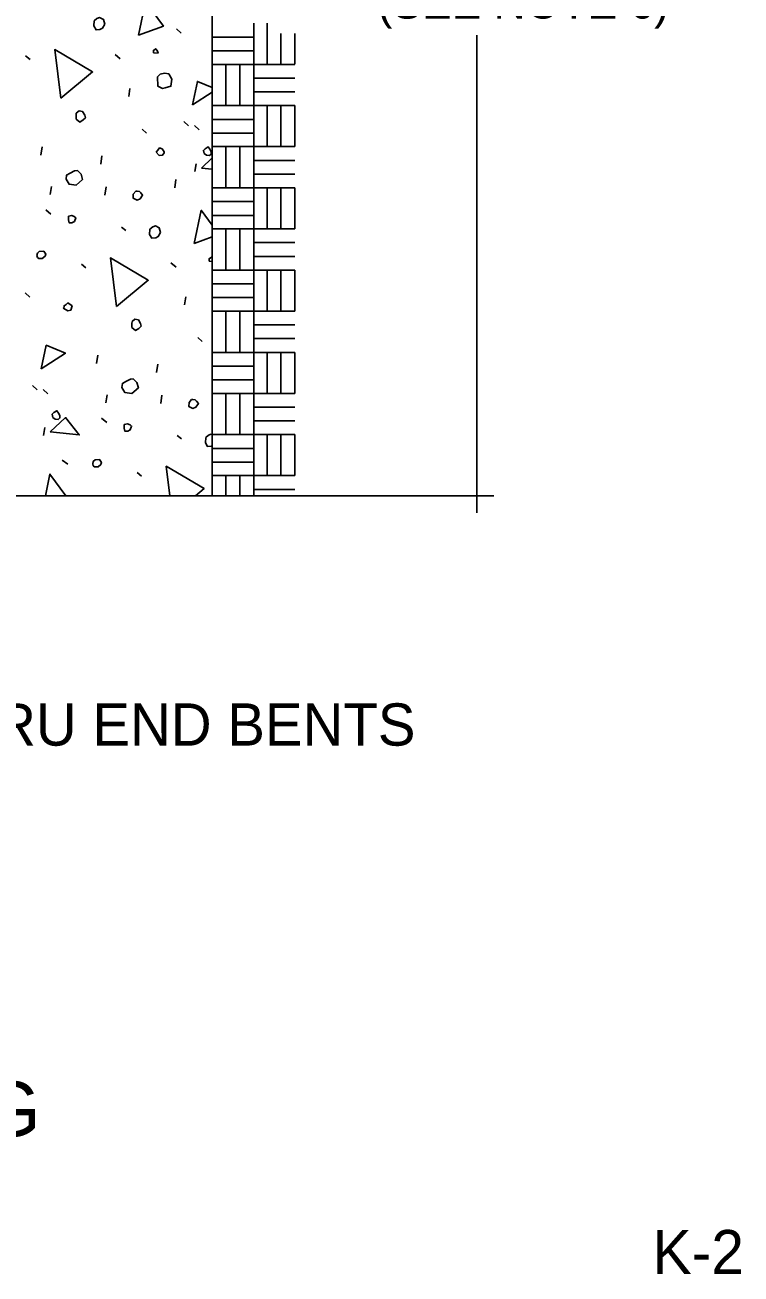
# Model space of a CAD drawing. Extents: x -1660015.2 to -1659984.9, y 2580594.2 to 2580616.7.
# Drawn here: x -1659988.32 to -1659985.07, y 2580594.23 to 2580599.91 of the extents above; entities that cross this region are included whole.
import ezdxf

# ---------------------------------------------------------------- set-up
doc = ezdxf.new("R2010")
doc.units = 0
for name, color, linetype in [('Miscellaneous', 7, 'Continuous'), ('Miscellaneous3', 7, 'Continuous'), ('Miscellaneous4', 7, 'Continuous'), ('PlotBorder_dp', 7, 'Continuous'), ('SheetLines_dp', 7, 'Continuous'), ('TextShtNo', 7, 'Continuous')]:
    doc.layers.add(name, color=color, linetype=linetype)

msp = doc.modelspace()

# ---------------------------------------------------------------- linework, layer by layer
at = {"layer": 'Miscellaneous'}
for p, q in [((-1659987.2832, 2580599.5396), (-1659987.2832, 2580599.9134)), ((-1659987.2219, 2580599.7271), (-1659987.2219, 2580599.9134)), ((-1659987.6339, 2580599.8883), (-1659987.613, 2580599.868)), ((-1659987.4719, 2580599.8509), (-1659987.2832, 2580599.8509)), ((-1659987.1594, 2580599.7272), (-1659987.1594, 2580599.8675)), ((-1659987.0969, 2580599.7272), (-1659987.0969, 2580599.8675)), ((-1659987.4719, 2580599.7884), (-1659987.2832, 2580599.7884)), ((-1659988.3208, 2580599.7663), (-1659988.3005, 2580599.7485)), ((-1659987.9134, 2580599.772), (-1659987.89, 2580599.7524)), ((-1659987.4719, 2580599.7271), (-1659987.0969, 2580599.7271)), ((-1659987.4094, 2580599.7271), (-1659987.4094, 2580599.5396)), ((-1659987.3469, 2580599.7271), (-1659987.3469, 2580599.5396)), ((-1659987.8519, 2580599.5814), (-1659987.8459, 2580599.6167)), ((-1659987.2832, 2580599.6646), (-1659987.0969, 2580599.6646)), ((-1659987.2832, 2580599.6021), (-1659987.0969, 2580599.6021)), ((-1659987.4719, 2580599.5396), (-1659987.2832, 2580599.5396)), ((-1659987.2832, 2580599.1659), (-1659987.2832, 2580599.5396)), ((-1659987.2832, 2580599.5396), (-1659987.0969, 2580599.5396)), ((-1659987.2219, 2580599.3534), (-1659987.2219, 2580599.5396)), ((-1659987.1594, 2580599.3534), (-1659987.1594, 2580599.5396)), ((-1659987.0969, 2580599.3534), (-1659987.0969, 2580599.5396)), ((-1659987.6014, 2580599.4673), (-1659987.5804, 2580599.4471)), ((-1659987.5526, 2580599.4494), (-1659987.5316, 2580599.4291)), ((-1659987.4719, 2580599.4771), (-1659987.2832, 2580599.4771)), ((-1659987.7912, 2580599.432), (-1659987.7709, 2580599.4142)), ((-1659987.4719, 2580599.4146), (-1659987.2832, 2580599.4146)), ((-1659988.2513, 2580599.3139), (-1659988.2459, 2580599.3516)), ((-1659987.4719, 2580599.3534), (-1659987.0969, 2580599.3534)), ((-1659987.4719, 2580599.3534), (-1659987.4719, 2580599.1659)), ((-1659987.4094, 2580599.3534), (-1659987.4094, 2580599.1659)), ((-1659987.3469, 2580599.3534), (-1659987.3469, 2580599.1659)), ((-1659987.9789, 2580599.273), (-1659987.9735, 2580599.3107)), ((-1659987.5509, 2580599.2402), (-1659987.5448, 2580599.2755)), ((-1659987.2832, 2580599.2909), (-1659987.0969, 2580599.2909)), ((-1659987.2832, 2580599.2284), (-1659987.0969, 2580599.2284)), ((-1659988.2089, 2580599.1363), (-1659988.2028, 2580599.1716)), ((-1659987.9596, 2580599.1332), (-1659987.9542, 2580599.1709)), ((-1659987.6424, 2580599.1665), (-1659987.637, 2580599.2042)), ((-1659987.4719, 2580599.1659), (-1659987.2832, 2580599.1659)), ((-1659987.2832, 2580599.1659), (-1659987.0969, 2580599.1659)), ((-1659987.2832, 2580598.7921), (-1659987.2832, 2580599.1659)), ((-1659987.2219, 2580598.9796), (-1659987.2219, 2580599.1659)), ((-1659987.1594, 2580598.9796), (-1659987.1594, 2580599.1659)), ((-1659987.0969, 2580598.9796), (-1659987.0969, 2580599.1659)), ((-1659987.4719, 2580599.1034), (-1659987.2832, 2580599.1034)), ((-1659988.229, 2580599.0663), (-1659988.2056, 2580599.0466)), ((-1659987.4719, 2580599.0409), (-1659987.2832, 2580599.0409)), ((-1659987.8844, 2580598.9878), (-1659987.8647, 2580598.9723)), ((-1659987.4719, 2580598.9796), (-1659987.0969, 2580598.9796)), ((-1659987.4719, 2580598.9796), (-1659987.4719, 2580598.7921)), ((-1659987.4094, 2580598.9796), (-1659987.4094, 2580598.7921)), ((-1659987.3469, 2580598.9796), (-1659987.3469, 2580598.7921)), ((-1659987.2832, 2580598.9171), (-1659987.0969, 2580598.9171)), ((-1659988.0671, 2580598.8197), (-1659988.0468, 2580598.8019)), ((-1659987.6597, 2580598.8254), (-1659987.6363, 2580598.8058)), ((-1659987.2832, 2580598.8546), (-1659987.0969, 2580598.8546)), ((-1659987.4719, 2580598.7921), (-1659987.2832, 2580598.7921)), ((-1659987.2832, 2580598.4184), (-1659987.2832, 2580598.7921)), ((-1659987.2832, 2580598.7921), (-1659987.0969, 2580598.7921)), ((-1659987.2219, 2580598.6059), (-1659987.2219, 2580598.7921)), ((-1659987.1594, 2580598.6059), (-1659987.1594, 2580598.7921)), ((-1659987.0969, 2580598.6059), (-1659987.0969, 2580598.7921)), ((-1659987.4719, 2580598.7296), (-1659987.2832, 2580598.7296)), ((-1659988.3221, 2580598.6893), (-1659988.3011, 2580598.669)), ((-1659987.5983, 2580598.6348), (-1659987.5922, 2580598.6701)), ((-1659987.4719, 2580598.6671), (-1659987.2832, 2580598.6671)), ((-1659987.4719, 2580598.6059), (-1659987.0969, 2580598.6059)), ((-1659987.4719, 2580598.6059), (-1659987.4719, 2580598.4184)), ((-1659987.4094, 2580598.6059), (-1659987.4094, 2580598.4184)), ((-1659987.3469, 2580598.6059), (-1659987.3469, 2580598.4184)), ((-1659987.2832, 2580598.5434), (-1659987.0969, 2580598.5434)), ((-1659987.5376, 2580598.4854), (-1659987.5173, 2580598.4676)), ((-1659987.2832, 2580598.4809), (-1659987.0969, 2580598.4809)), ((-1659987.9977, 2580598.3673), (-1659987.9922, 2580598.405)), ((-1659987.4719, 2580598.4184), (-1659987.2832, 2580598.4184)), ((-1659987.2832, 2580598.4184), (-1659987.0969, 2580598.4184)), ((-1659987.2832, 2580598.0446), (-1659987.2832, 2580598.4184)), ((-1659987.2219, 2580598.2321), (-1659987.2219, 2580598.4184)), ((-1659987.1594, 2580598.2321), (-1659987.1594, 2580598.4184)), ((-1659987.0969, 2580598.2321), (-1659987.0969, 2580598.4184)), ((-1659987.7253, 2580598.3264), (-1659987.7199, 2580598.3641)), ((-1659987.4719, 2580598.3559), (-1659987.2832, 2580598.3559)), ((-1659988.2895, 2580598.2684), (-1659988.2686, 2580598.2481)), ((-1659987.4719, 2580598.2934), (-1659987.2832, 2580598.2934)), ((-1659988.2407, 2580598.2504), (-1659988.2197, 2580598.2301)), ((-1659987.9553, 2580598.1897), (-1659987.9492, 2580598.225)), ((-1659987.706, 2580598.1866), (-1659987.7005, 2580598.2243)), ((-1659987.4719, 2580598.2321), (-1659987.0969, 2580598.2321)), ((-1659987.4719, 2580598.2321), (-1659987.4719, 2580598.0446)), ((-1659987.4094, 2580598.2321), (-1659987.4094, 2580598.0446)), ((-1659987.3469, 2580598.2321), (-1659987.3469, 2580598.0446)), ((-1659987.2832, 2580598.1696), (-1659987.0969, 2580598.1696)), ((-1659987.9753, 2580598.1196), (-1659987.9519, 2580598.1)), ((-1659987.2832, 2580598.1071), (-1659987.0969, 2580598.1071)), ((-1659988.239, 2580598.0412), (-1659988.2329, 2580598.0765)), ((-1659987.6308, 2580598.0411), (-1659987.6111, 2580598.0257)), ((-1659987.4719, 2580598.0446), (-1659987.2832, 2580598.0446)), ((-1659987.2832, 2580597.7672), (-1659987.2832, 2580598.0447)), ((-1659987.2832, 2580598.0446), (-1659987.0969, 2580598.0446)), ((-1659987.2219, 2580597.8584), (-1659987.2219, 2580598.0446)), ((-1659987.1594, 2580597.8584), (-1659987.1594, 2580598.0446)), ((-1659987.0969, 2580597.8584), (-1659987.0969, 2580598.0446)), ((-1659987.4719, 2580597.9821), (-1659987.2832, 2580597.9821)), ((-1659988.1546, 2580597.9292), (-1659988.1289, 2580597.9103)), ((-1659987.4719, 2580597.9196), (-1659987.2832, 2580597.9196)), ((-1659987.8135, 2580597.8731), (-1659987.7932, 2580597.8553)), ((-1659987.4719, 2580597.8584), (-1659987.0969, 2580597.8584)), ((-1659987.4094, 2580597.8584), (-1659987.4094, 2580597.7672)), ((-1659987.3469, 2580597.8584), (-1659987.3469, 2580597.7672)), ((-1659987.2832, 2580597.7959), (-1659987.0969, 2580597.7959))]:
    msp.add_line(p, q, dxfattribs=at)
for points in [[(-1659987.8075, 2580599.8599), (-1659987.7755, 2580600.0108), (-1659987.6942, 2580599.9006), (-1659987.8075, 2580599.8599)], [(-1659988.0087, 2580599.925), (-1659988.0101, 2580599.9013), (-1659988.0001, 2580599.8833), (-1659987.9826, 2580599.8854), (-1659987.9712, 2580599.8911), (-1659987.9605, 2580599.9095), (-1659987.9664, 2580599.9312), (-1659987.9841, 2580599.9394), (-1659987.9962, 2580599.9361), (-1659988.0087, 2580599.925)], [(-1659988.1605, 2580599.5738), (-1659988.1884, 2580599.794), (-1659988.0163, 2580599.6926), (-1659988.1605, 2580599.5738)], [(-1659987.7394, 2580599.7798), (-1659987.7182, 2580599.7777), (-1659987.7208, 2580599.7873), (-1659987.7288, 2580599.7981), (-1659987.7396, 2580599.7901), (-1659987.7394, 2580599.7798)], [(-1659987.7206, 2580599.6709), (-1659987.7193, 2580599.6273), (-1659987.6985, 2580599.6173), (-1659987.6864, 2580599.6206), (-1659987.6599, 2580599.6277), (-1659987.6556, 2580599.6599), (-1659987.6699, 2580599.6845), (-1659987.6888, 2580599.6872), (-1659987.7081, 2580599.682), (-1659987.7206, 2580599.6709)], [(-1659987.562, 2580599.5426), (-1659987.539, 2580599.6497), (-1659987.472, 2580599.622)], [(-1659987.472, 2580599.6005), (-1659987.562, 2580599.5426)], [(-1659988.0907, 2580599.4967), (-1659988.091, 2580599.4785), (-1659988.0744, 2580599.4648), (-1659988.0587, 2580599.4742), (-1659988.0486, 2580599.4847), (-1659988.0518, 2580599.4968), (-1659988.0612, 2580599.5124), (-1659988.0776, 2580599.5157), (-1659988.0902, 2580599.5046), (-1659988.0907, 2580599.4967)], [(-1659987.727, 2580599.3276), (-1659987.7128, 2580599.3133), (-1659987.6977, 2580599.3147), (-1659987.6899, 2580599.3246), (-1659987.6912, 2580599.3294), (-1659987.7, 2580599.3426), (-1659987.7116, 2580599.3472), (-1659987.7193, 2580599.3374), (-1659987.727, 2580599.3276)], [(-1659987.508, 2580599.3216), (-1659987.4981, 2580599.3138), (-1659987.4848, 2580599.3122), (-1659987.4764, 2580599.3197), (-1659987.4766, 2580599.33), (-1659987.4822, 2580599.3414), (-1659987.4903, 2580599.3522), (-1659987.5035, 2580599.3435), (-1659987.5119, 2580599.336), (-1659987.508, 2580599.3216)], [(-1659987.5214, 2580599.2558), (-1659987.472, 2580599.3018)], [(-1659988.1367, 2580599.2049), (-1659988.123, 2580599.1826), (-1659988.0908, 2580599.1783), (-1659988.0615, 2580599.2043), (-1659988.068, 2580599.2285), (-1659988.0852, 2580599.2445), (-1659988.0979, 2580599.2437), (-1659988.1184, 2580599.2331), (-1659988.134, 2580599.2237), (-1659988.1367, 2580599.2049)], [(-1659987.472, 2580599.2508), (-1659987.5214, 2580599.2558)], [(-1659987.8311, 2580599.1366), (-1659987.8314, 2580599.1184), (-1659987.8137, 2580599.1102), (-1659987.7998, 2580599.1165), (-1659987.7886, 2580599.1325), (-1659987.7967, 2580599.1433), (-1659987.8034, 2580599.1492), (-1659987.8144, 2580599.1515), (-1659987.8192, 2580599.1502), (-1659987.8311, 2580599.1366)], [(-1659987.5539, 2580598.9133), (-1659987.5218, 2580599.0642), (-1659987.472, 2580598.9966)], [(-1659988.1263, 2580599.0213), (-1659988.1224, 2580599.0068), (-1659988.1097, 2580599.0076), (-1659988.0983, 2580599.0133), (-1659988.0925, 2580599.0303), (-1659988.0993, 2580599.0363), (-1659988.1109, 2580599.0409), (-1659988.1254, 2580599.0371), (-1659988.1263, 2580599.0213)], [(-1659987.7551, 2580598.9784), (-1659987.7565, 2580598.9547), (-1659987.7465, 2580598.9367), (-1659987.7289, 2580598.9388), (-1659987.7175, 2580598.9445), (-1659987.7069, 2580598.9628), (-1659987.7127, 2580598.9846), (-1659987.7305, 2580598.9928), (-1659987.7425, 2580598.9895), (-1659987.7551, 2580598.9784)], [(-1659987.472, 2580598.9427), (-1659987.5539, 2580598.9133)], [(-1659988.2665, 2580598.8491), (-1659988.2604, 2580598.8456), (-1659988.2446, 2580598.8446), (-1659988.2321, 2580598.8558), (-1659988.2292, 2580598.8643), (-1659988.2379, 2580598.8775), (-1659988.2585, 2580598.8772), (-1659988.2669, 2580598.8697), (-1659988.2691, 2580598.8588), (-1659988.2665, 2580598.8491)], [(-1659987.9068, 2580598.6272), (-1659987.9348, 2580598.8474), (-1659987.7627, 2580598.746), (-1659987.9068, 2580598.6272)], [(-1659987.472, 2580598.8472), (-1659987.4752, 2580598.8515), (-1659987.486, 2580598.8435), (-1659987.4858, 2580598.8332)], [(-1659987.4858, 2580598.8332), (-1659987.472, 2580598.8318)], [(-1659988.1474, 2580598.617), (-1659988.129, 2580598.6064), (-1659988.1146, 2580598.6103), (-1659988.1094, 2580598.6298), (-1659988.1284, 2580598.6428), (-1659988.1368, 2580598.6354), (-1659988.1458, 2580598.6304), (-1659988.1474, 2580598.617), (-1659988.1487, 2580598.6219)], [(-1659987.837, 2580598.5501), (-1659987.8373, 2580598.5319), (-1659987.8207, 2580598.5182), (-1659987.8051, 2580598.5276), (-1659987.795, 2580598.5381), (-1659987.7982, 2580598.5502), (-1659987.8076, 2580598.5658), (-1659987.824, 2580598.5691), (-1659987.8365, 2580598.558), (-1659987.837, 2580598.5501)], [(-1659988.2502, 2580598.3436), (-1659988.2271, 2580598.4508), (-1659988.1398, 2580598.4146), (-1659988.2502, 2580598.3436)], [(-1659987.472, 2580598.3827), (-1659987.4733, 2580598.381)], [(-1659987.4733, 2580598.381), (-1659987.472, 2580598.3796)], [(-1659987.883, 2580598.2582), (-1659987.8693, 2580598.236), (-1659987.8371, 2580598.2317), (-1659987.8078, 2580598.2577), (-1659987.8143, 2580598.2818), (-1659987.8316, 2580598.2979), (-1659987.8443, 2580598.2971), (-1659987.8647, 2580598.2865), (-1659987.8803, 2580598.2771), (-1659987.883, 2580598.2582)], [(-1659987.5775, 2580598.19), (-1659987.5778, 2580598.1718), (-1659987.56, 2580598.1636), (-1659987.5462, 2580598.1699), (-1659987.535, 2580598.1859), (-1659987.543, 2580598.1967), (-1659987.5498, 2580598.2026), (-1659987.5607, 2580598.2048), (-1659987.5656, 2580598.2036), (-1659987.5775, 2580598.19)], [(-1659988.1961, 2580598.1226), (-1659988.1863, 2580598.1149), (-1659988.1729, 2580598.1133), (-1659988.1645, 2580598.1207), (-1659988.1647, 2580598.131), (-1659988.1704, 2580598.1424), (-1659988.1784, 2580598.1532), (-1659988.1916, 2580598.1445), (-1659988.2, 2580598.1371), (-1659988.1961, 2580598.1226)], [(-1659988.2096, 2580598.0569), (-1659988.1391, 2580598.1223), (-1659988.0765, 2580598.0434), (-1659988.2096, 2580598.0569)], [(-1659987.8727, 2580598.0747), (-1659987.8688, 2580598.0602), (-1659987.8561, 2580598.061), (-1659987.8446, 2580598.0667), (-1659987.8389, 2580598.0837), (-1659987.8456, 2580598.0897), (-1659987.8572, 2580598.0943), (-1659987.8717, 2580598.0905), (-1659987.8727, 2580598.0747)], [(-1659987.5014, 2580598.0318), (-1659987.5029, 2580598.0081), (-1659987.4928, 2580597.9901), (-1659987.4753, 2580597.9922), (-1659987.472, 2580597.9939)], [(-1659987.472, 2580598.0439), (-1659987.4768, 2580598.0462), (-1659987.4889, 2580598.0429), (-1659987.5014, 2580598.0318)], [(-1659988.0129, 2580597.9025), (-1659988.0068, 2580597.899), (-1659987.991, 2580597.898), (-1659987.9784, 2580597.9092), (-1659987.9756, 2580597.9177), (-1659987.9843, 2580597.9309), (-1659988.0049, 2580597.9305), (-1659988.0132, 2580597.9231), (-1659988.0155, 2580597.9122), (-1659988.0129, 2580597.9025)], [(-1659988.2308, 2580597.7673), (-1659988.21, 2580597.8652), (-1659988.1377, 2580597.7673)], [(-1659987.6642, 2580597.7673), (-1659987.6812, 2580597.9008), (-1659987.509, 2580597.7994), (-1659987.548, 2580597.7673)]]:
    msp.add_lwpolyline(points, dxfattribs=at)
at = {"layer": 'Miscellaneous3'}
msp.add_line((-1659987.472, 2580597.7672), (-1659987.472, 2580602.2354), dxfattribs=at)
at = {"layer": 'SheetLines_dp'}
for points in [[(-1659986.2685, 2580597.6897), (-1659986.2685, 2580599.8593)], [(-1659986.1909, 2580597.7671), (-1659989.4814, 2580597.7671), (-1659989.4814, 2580597.8446), (-1659989.5152, 2580597.7671), (-1659989.5489, 2580597.6896), (-1659989.5489, 2580597.7671), (-1659992.7319, 2580597.7671)]]:
    msp.add_lwpolyline(points, dxfattribs=at)

# ---------------------------------------------------------------- texts
at = {"layer": 'Miscellaneous4'}
msp.add_text('MAINTENANCE LIGHTING', height=0.25001, rotation=360, dxfattribs=at).set_placement((-1659992.3581, 2580594.8559))
at = {"layer": 'PlotBorder_dp'}
msp.add_text('STEEL BOX GIRDER BRIDGE SECTION THRU END BENTS', height=0.192, dxfattribs=at).set_placement((-1659993.6377, 2580596.6316))
at = {"layer": 'SheetLines_dp'}
msp.add_text('(SEE NOTE 6)', height=0.1512, dxfattribs=at).set_placement((-1659986.7203, 2580599.935))
at = {"layer": 'TextShtNo'}
msp.add_text('K-2', height=0.2, dxfattribs=at).set_placement((-1659985.4697, 2580594.2309))

doc.saveas('drawing.dxf')
